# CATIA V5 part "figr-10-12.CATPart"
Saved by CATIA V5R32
Part number: Part1
Bounding box of the stored display mesh (mm): x -100 to 0, y -100 to 90, z 0 to 33.63
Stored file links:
  D:\PROJECTS\Project 2022\CATIA V5 6R 2022\Resources\Part Files\c10_catia_v5_6r2022_prt\c10_catia_v5_6r2022_prt\figr-10-12.CATPart
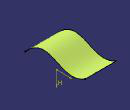
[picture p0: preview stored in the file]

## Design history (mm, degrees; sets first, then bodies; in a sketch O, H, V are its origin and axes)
Set1
  Sketch1 on face of yz-plane, origin (0, 0, 0), H (0, 0, -1), V (0, 1, 0)
    spline S1 through (0, -100) (-30, -20) (-10, 30) (-20, 90)
  Extrude1: Element1 Sketch1, Lim1 0, Lim2 100, Direction face of yz-plane
Body1 (main body)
